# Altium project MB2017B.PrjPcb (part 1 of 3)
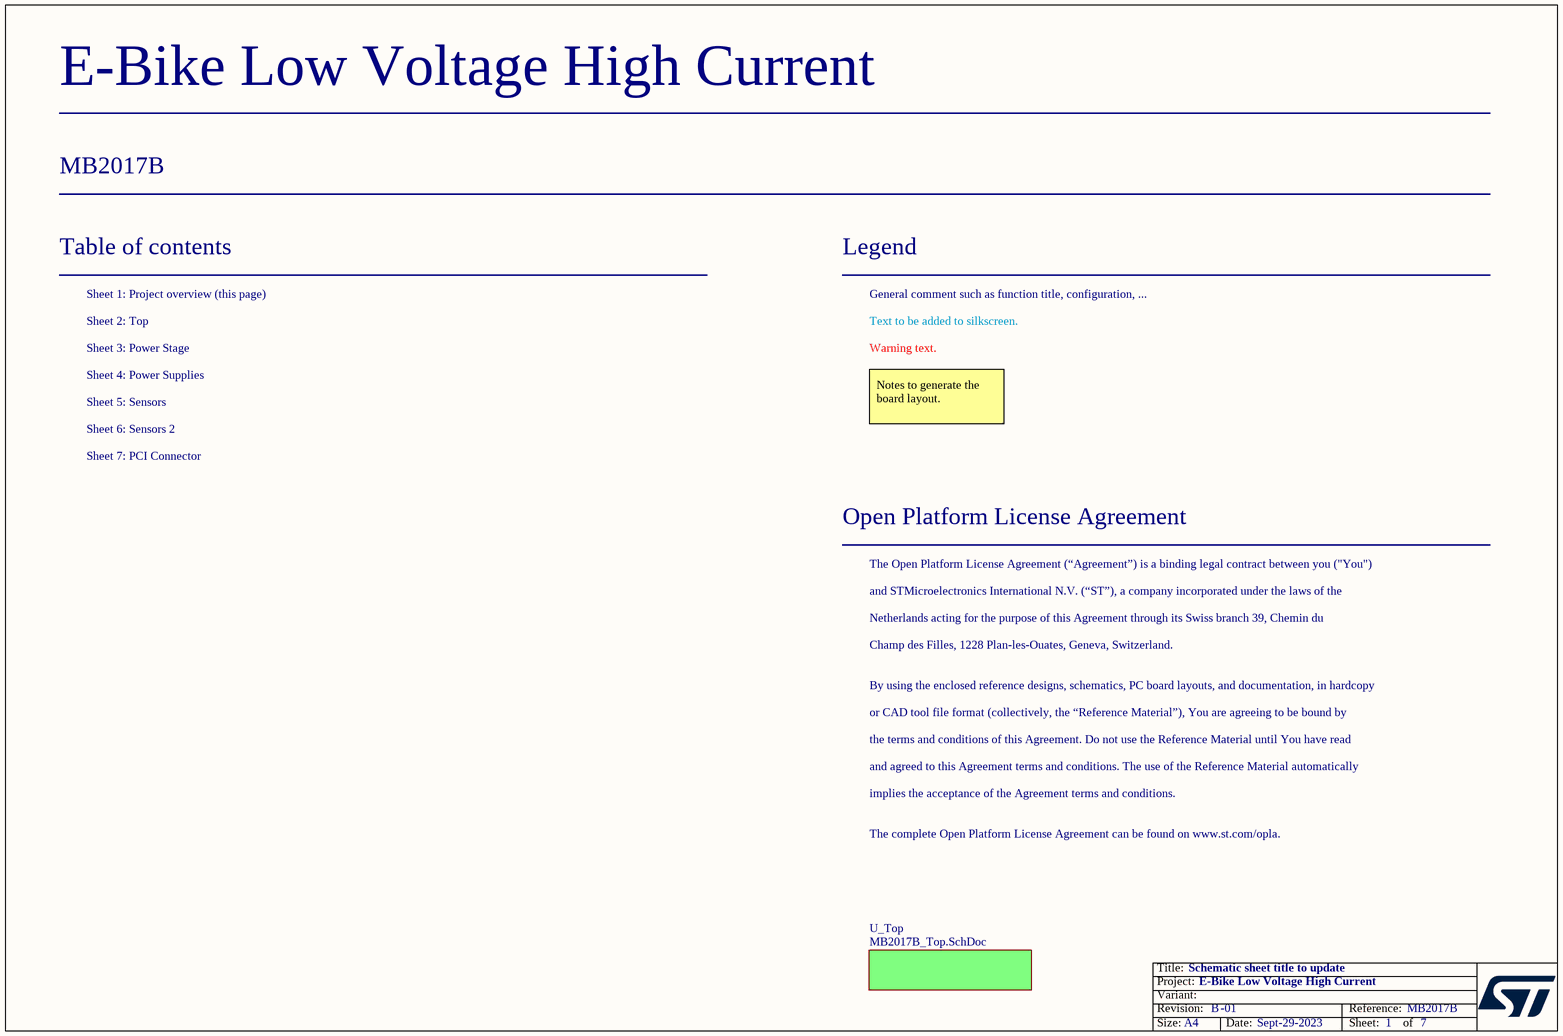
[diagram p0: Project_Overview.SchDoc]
Board_Assembly_Revision: 01; Board_Document_Date: Sept-29-2023; Board_Name: E-Bike Low Voltage High Current; Board_PCB_Revision: B; Board_Reference: MB2017B
7 sheets, 469 parts. Net scope: flat (ports and power ports of the same name join across sheets).
Board file: MB2017B.PcbDoc
Sheets:
  Project_Overview.SchDoc
    U_Top = MB2017B_Top.SchDoc
      U_Power_Supplies = Power_Supplies.SchDoc
      U_PCI_Connector = PCI_Connector.SchDoc
      U_Power_Stage = Power_Stage.SchDoc
      U_Sensors = Sensors.SchDoc
      U_Sensors_2 = Sensors_2.SchDoc

## Sheet Project_Overview.SchDoc: Schematic sheet title to update
size A4; Date: Not used; ApprovedBy: Not used; CheckedBy: Not used; Author: Not used; CompanyName: STMicroelectronics; DrawnBy: Not used; Engineer: Not used; Organization: Not used; Address1: Not used; Address2: Not used; Address3: Not used; Address4: Not used; DocumentNumber: Not used; Revision: Not used; SheetNumber: 1; SheetTotal: 7

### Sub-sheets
U_Top = MB2017B_Top.SchDoc: no entries

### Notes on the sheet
- Table of contents
- Sheet 1: Project overview (this page)
- Legend
- General comment such as function title, configuration, ...
- Sheet 2: Top
- Sheet 3: Power Stage
- Sheet 4: Power Supplies
- Text to be added to silkscreen.
- Warning text.
- Sheet 5: Sensors
- Sheet 6: Sensors 2
- Notes to generate the board layout.
- Sheet 7: PCI Connector
- Open Platform License Agreement
- The Open Platform License Agreement (“Agreement”) is a binding legal contract between you ("You")
- and STMicroelectronics International N.V. (“ST”), a company incorporated under the laws of the
- Netherlands acting for the purpose of this Agreement through its Swiss branch 39, Chemin du
- Champ des Filles, 1228 Plan-les-Ouates, Geneva, Switzerland.
- By using the enclosed reference designs, schematics, PC board layouts, and documentation, in hardcopy
- or CAD tool file format (collectively, the “Reference Material”), You are agreeing to be bound by
- the terms and conditions of this Agreement. Do not use the Reference Material until You have read
- and agreed to this Agreement terms and conditions. The use of the Reference Material automatically
- implies the acceptance of the Agreement terms and conditions.
- The complete Open Platform License Agreement can be found on www.st.com/opla.

## Sheet MB2017B_Top.SchDoc: Top
size A4; Date: Not used; ApprovedBy: Not used; CheckedBy: Not used; Author: Not used; CompanyName: STMicroelectronics; DrawnBy: Not used; Engineer: Not used; Organization: Not used; Address1: Not used; Address2: Not used; Address3: Not used; Address4: Not used; DocumentNumber: Not used; Revision: Not used; SheetNumber: 2; SheetTotal: 7
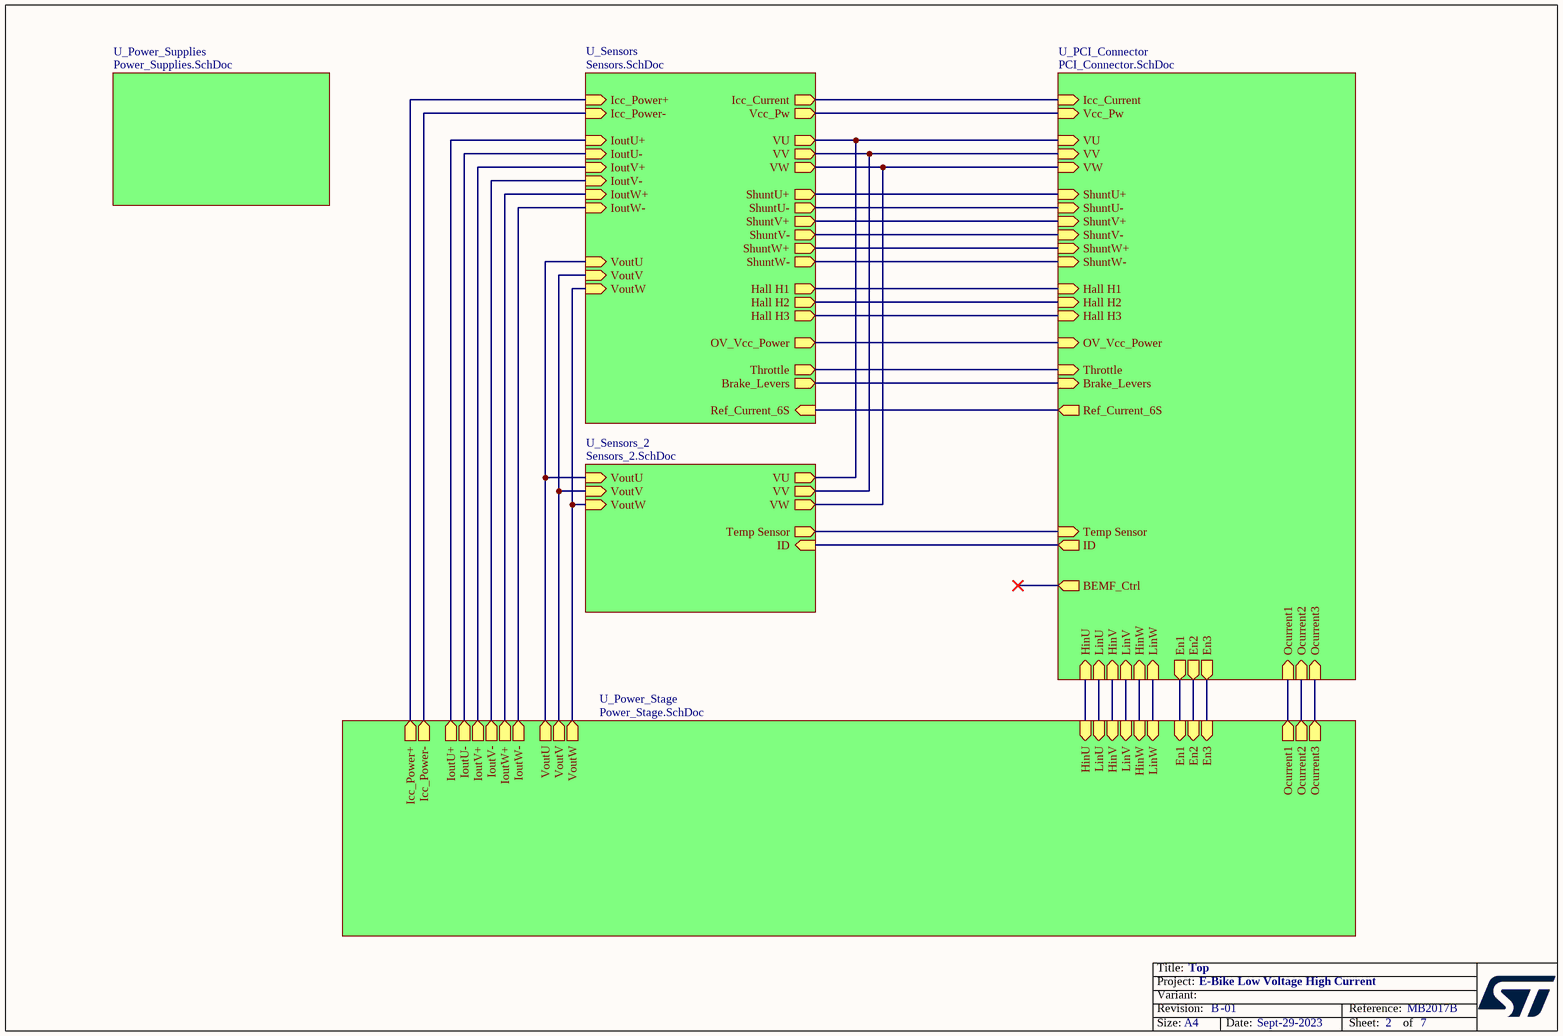
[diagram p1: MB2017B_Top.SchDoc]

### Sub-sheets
U_PCI_Connector = PCI_Connector.SchDoc: BEMF_Ctrl (out), HinU (in), LinU (in), HinV (in), LinV (in), HinW (in), LinW (in), Hall H1 (in), Hall H2 (in), Hall H3 (in), ShuntU- (in), ShuntU+ (in), ShuntV- (in), ShuntV+ (in), ShuntW- (in), ShuntW+ (in), VU (in), VV (in), VW (in), Temp Sensor (in), OV_Vcc_Power (in), Brake_Levers (in), Ref_Current_6S (out), Icc_Current (in), Throttle (in), Vcc_Pw (in), Ocurrent2 (in), En3 (out), Ocurrent3 (in), En1 (out), En2 (out), Ocurrent1 (in), ID (out)
U_Power_Stage = Power_Stage.SchDoc: VoutU (out), IoutU+ (out), IoutU- (out), HinU (in), LinU (in), IoutV+ (out), IoutV- (out), HinV (in), LinV (in), VoutW (out), IoutW+ (out), IoutW- (out), HinW (in), LinW (in), Icc_Power+ (out), Icc_Power- (out), En1 (in), En2 (in), Ocurrent3 (out), Ocurrent2 (out), En3 (in), Ocurrent1 (out), VoutV (out)
U_Power_Supplies = Power_Supplies.SchDoc: no entries
U_Sensors = Sensors.SchDoc: Icc_Power+ (in), Icc_Power- (in), Icc_Current (out), IoutU+ (in), IoutU- (in), IoutV+ (in), IoutV- (in), IoutW+ (in), IoutW- (in), VoutU (in), VoutV (in), VoutW (in), VU (out), VV (out), VW (out), ShuntU- (out), ShuntV- (out), ShuntW- (out), ShuntU+ (out), ShuntV+ (out), ShuntW+ (out), OV_Vcc_Power (out), Hall H1 (out), Hall H2 (out), Hall H3 (out), Throttle (out), Brake_Levers (out), Vcc_Pw (out), Ref_Current_6S (in)
U_Sensors_2 = Sensors_2.SchDoc: VoutU (in), VU (out), VoutV (in), VoutW (in), VW (out), VV (out), Temp Sensor (out), ID (in)

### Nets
(unnamed): sheet U_PCI_Connector/HinU, sheet U_Power_Stage/HinU
(unnamed): sheet U_PCI_Connector/LinU, sheet U_Power_Stage/LinU  [a separate net that carries the same name]
(unnamed): sheet U_PCI_Connector/HinV, sheet U_Power_Stage/HinV  [a separate net that carries the same name]
(unnamed): sheet U_PCI_Connector/LinV, sheet U_Power_Stage/LinV  [a separate net that carries the same name]
(unnamed): sheet U_PCI_Connector/HinW, sheet U_Power_Stage/HinW  [a separate net that carries the same name]
(unnamed): sheet U_PCI_Connector/LinW, sheet U_Power_Stage/LinW  [a separate net that carries the same name]
(unnamed): sheet U_PCI_Connector/Hall H1, sheet U_Sensors/Hall H1  [a separate net that carries the same name]
(unnamed): sheet U_PCI_Connector/Hall H2, sheet U_Sensors/Hall H2  [a separate net that carries the same name]
(unnamed): sheet U_PCI_Connector/Hall H3, sheet U_Sensors/Hall H3  [a separate net that carries the same name]
(unnamed): sheet U_PCI_Connector/ShuntU-, sheet U_Sensors/ShuntU-  [a separate net that carries the same name]
(unnamed): sheet U_PCI_Connector/ShuntU+, sheet U_Sensors/ShuntU+  [a separate net that carries the same name]
(unnamed): sheet U_PCI_Connector/ShuntV-, sheet U_Sensors/ShuntV-  [a separate net that carries the same name]
(unnamed): sheet U_PCI_Connector/ShuntV+, sheet U_Sensors/ShuntV+  [a separate net that carries the same name]
(unnamed): sheet U_PCI_Connector/ShuntW-, sheet U_Sensors/ShuntW-  [a separate net that carries the same name]
(unnamed): sheet U_PCI_Connector/ShuntW+, sheet U_Sensors/ShuntW+  [a separate net that carries the same name]
(unnamed): sheet U_PCI_Connector/VU, sheet U_Sensors/VU, sheet U_Sensors_2/VU  [a separate net that carries the same name]
(unnamed): sheet U_PCI_Connector/VV, sheet U_Sensors/VV, sheet U_Sensors_2/VV  [a separate net that carries the same name]
(unnamed): sheet U_PCI_Connector/VW, sheet U_Sensors/VW, sheet U_Sensors_2/VW  [a separate net that carries the same name]
(unnamed): sheet U_PCI_Connector/Temp Sensor, sheet U_Sensors_2/Temp Sensor  [a separate net that carries the same name]
(unnamed): sheet U_PCI_Connector/OV_Vcc_Power, sheet U_Sensors/OV_Vcc_Power  [a separate net that carries the same name]
(unnamed): sheet U_PCI_Connector/Brake_Levers, sheet U_Sensors/Brake_Levers  [a separate net that carries the same name]
(unnamed): sheet U_PCI_Connector/Ref_Current_6S, sheet U_Sensors/Ref_Current_6S  [a separate net that carries the same name]
(unnamed): sheet U_PCI_Connector/Icc_Current, sheet U_Sensors/Icc_Current  [a separate net that carries the same name]
(unnamed): sheet U_PCI_Connector/Throttle, sheet U_Sensors/Throttle  [a separate net that carries the same name]
(unnamed): sheet U_PCI_Connector/Vcc_Pw, sheet U_Sensors/Vcc_Pw  [a separate net that carries the same name]
(unnamed): sheet U_PCI_Connector/Ocurrent2, sheet U_Power_Stage/Ocurrent2  [a separate net that carries the same name]
(unnamed): sheet U_PCI_Connector/En3, sheet U_Power_Stage/En3  [a separate net that carries the same name]
(unnamed): sheet U_PCI_Connector/Ocurrent3, sheet U_Power_Stage/Ocurrent3  [a separate net that carries the same name]
(unnamed): sheet U_PCI_Connector/En1, sheet U_Power_Stage/En1  [a separate net that carries the same name]
(unnamed): sheet U_PCI_Connector/En2, sheet U_Power_Stage/En2  [a separate net that carries the same name]
(unnamed): sheet U_PCI_Connector/Ocurrent1, sheet U_Power_Stage/Ocurrent1  [a separate net that carries the same name]
(unnamed): sheet U_PCI_Connector/ID, sheet U_Sensors_2/ID  [a separate net that carries the same name]
(unnamed): sheet U_Power_Stage/VoutU, sheet U_Sensors/VoutU, sheet U_Sensors_2/VoutU  [a separate net that carries the same name]
(unnamed): sheet U_Power_Stage/IoutU+, sheet U_Sensors/IoutU+  [a separate net that carries the same name]
(unnamed): sheet U_Power_Stage/IoutU-, sheet U_Sensors/IoutU-  [a separate net that carries the same name]
(unnamed): sheet U_Power_Stage/IoutV+, sheet U_Sensors/IoutV+  [a separate net that carries the same name]
(unnamed): sheet U_Power_Stage/IoutV-, sheet U_Sensors/IoutV-  [a separate net that carries the same name]
(unnamed): sheet U_Power_Stage/VoutW, sheet U_Sensors/VoutW, sheet U_Sensors_2/VoutW  [a separate net that carries the same name]
(unnamed): sheet U_Power_Stage/IoutW+, sheet U_Sensors/IoutW+  [a separate net that carries the same name]
(unnamed): sheet U_Power_Stage/IoutW-, sheet U_Sensors/IoutW-  [a separate net that carries the same name]
(unnamed): sheet U_Power_Stage/Icc_Power+, sheet U_Sensors/Icc_Power+  [a separate net that carries the same name]
(unnamed): sheet U_Power_Stage/Icc_Power-, sheet U_Sensors/Icc_Power-  [a separate net that carries the same name]
(unnamed): sheet U_Power_Stage/VoutV, sheet U_Sensors/VoutV, sheet U_Sensors_2/VoutV  [a separate net that carries the same name]

## Sheet Power_Supplies.SchDoc: Power Supplies
size A3; Date: Not used; ApprovedBy: Not used; CheckedBy: Not used; Author: Not used; CompanyName: STMicroelectronics; DrawnBy: Not used; Engineer: Not used; Organization: Not used; Address1: Not used; Address2: Not used; Address3: Not used; Address4: Not used; DocumentNumber: Not used; Revision: Not used; SheetNumber: 4; SheetTotal: 7
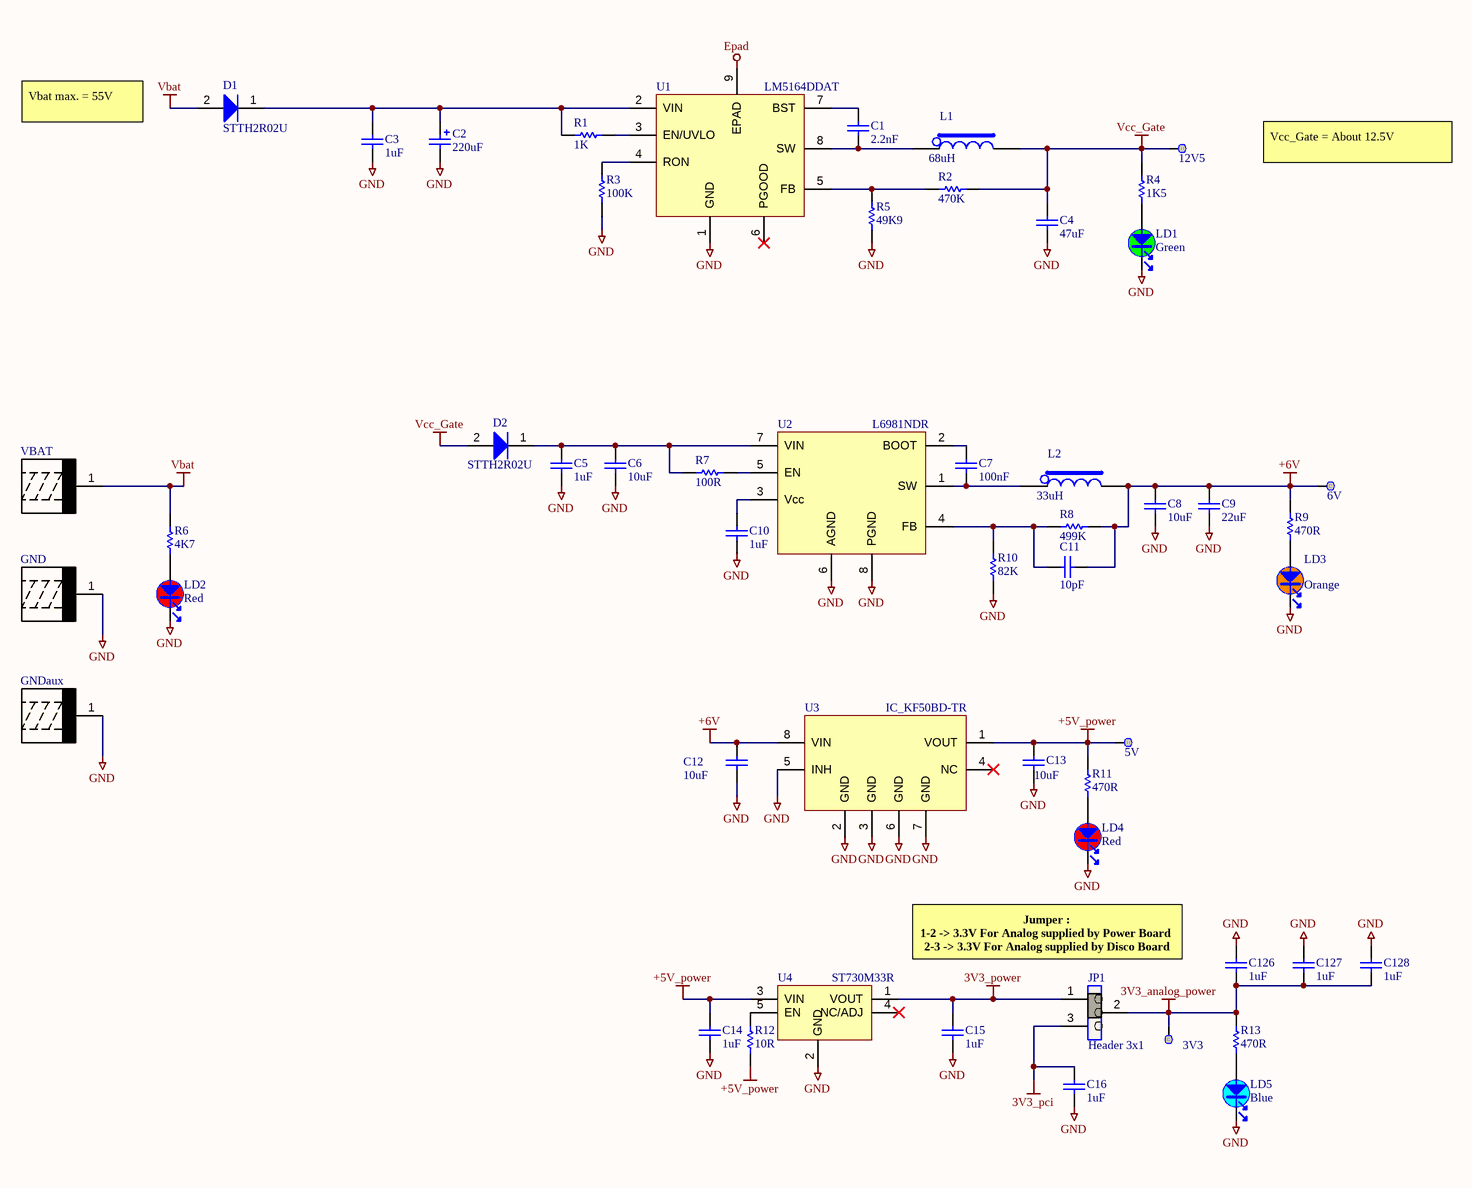
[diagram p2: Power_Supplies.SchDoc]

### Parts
3V3  Test Point  [TP_SMD_1MM]  (value not drawn)  (no BOM)
5V  Test Point  [TP_SMD_1MM]  (value not drawn)  (no BOM)
6V  Test Point  [TP_SMD_1MM]  (value not drawn)  (no BOM)
12V5  Test Point  [TP_SMD_1MM]  (value not drawn)  (no BOM)
C1  value 2.2nF  [C0603_H0P8]  (hidden comment: Capacitor)
C2  value 220uF  [CPOL_TDK_B41858C9227M000_H25]  (hidden comment: Cap_POL_TANA)
C3  value 1uF  [C1206_H1P6]  (hidden comment: Capacitor)
C4  value 47uF  [C1206_H1P6]  (hidden comment: Capacitor)
C5  value 1uF  [C0805_H0P85]  (hidden comment: Capacitor)
C6  value 10uF  [C1206_H1P6]  (hidden comment: Capacitor)
C7  value 100nF  [C0805_H0P85]  (hidden comment: Capacitor)
C8  value 10uF  [C1206_H1P6]  (hidden comment: Capacitor)
C9  value 22uF  [C1206_H1P6]  (hidden comment: Capacitor)
C10  value 1uF  [C0805_H0P85]  (hidden comment: Capacitor)
C11  value 10pF  [C0603]  (hidden comment: Capacitor)
C12  value 10uF  [C1206_H1P6]  (hidden comment: Capacitor)
C13  value 10uF  [C1206_H1P6]  (hidden comment: Capacitor)
C14  value 1uF  [C0805_H0P85]  (hidden comment: Capacitor)
C15  value 1uF  [C0805_H0P85]  (hidden comment: Capacitor)
C16  value 1uF  [C0805_H0P85]  (hidden comment: Capacitor)
C126  value 1uF  [C0805_H0P85]  (hidden comment: Capacitor)
C127  value 1uF  [C0805_H0P85]  (hidden comment: Capacitor)
C128  value 1uF  [C0805_H0P85]  (hidden comment: Capacitor)
D1  value STTH2R02U  [DIO_SMB_1K_2A]  (hidden comment: DIODE_1K_2A)
D2  value STTH2R02U  [DIO_SMB_1K_2A]  (hidden comment: DIODE_1K_2A)
GND  CON_M4_SNAP_IN_THR_KEYSTONE_7798  [CON_KEYSTONE_M4-SNAP_7798]  (value not drawn)
GNDaux  CON_M4_SNAP_IN_THR_KEYSTONE_7798  [CON_KEYSTONE_M4-SNAP_7798]  (value not drawn)
JP1  value Header 3x1  [CON_SAMTEC_TSW-103-07-F-S]  (hidden comment: Jumper_Header 3x1 Fitted 1-2)
L1  value 68uH  [IND_WURTH_7447714680]  (hidden comment: INDUCTOR_POWER_WINDING)
L2  value 33uH  [IND_COILCRAFT_MSS1038T-333MLC]  (hidden comment: INDUCTOR_POWER_WINDING)
LD1  value Green  [LED_0603_VISHAY_VLMTG1300-GS08_GREEN_1A2K_H0P8]  (hidden comment: LED_green)
LD2  value Red  [LED_0603_VISHAY_VLMS1300-GS08_RED_1A2K_H0P8]  (hidden comment: LED_red)
LD3  value Orange  [LED_0603_VISHAY_VLMO1300-GS08_ORANGE_1A2K_H0P8]  (hidden comment: LED_orange)
LD4  value Red  [LED_0603_VISHAY_VLMS1300-GS08_RED_1A2K_H0P8]  (hidden comment: LED_red)
LD5  value Blue  [LED_0603_VISHAY_VLMB1300-GS08_BLUE_1A2K_H0P8]  (hidden comment: LED_blue)
R1  value 1K  [R0603]  (hidden comment: Resistor)
R2  value 470K  [R0603]  (hidden comment: Resistor)
R3  value 100K  [R0603]  (hidden comment: Resistor)
R4  value 1K5  [R0805]  (hidden comment: Resistor)
R5  value 49K9  [R0603]  (hidden comment: Resistor)
R6  value 4K7  [R0805]  (hidden comment: Resistor)
R7  value 100R  [R0603]  (hidden comment: Resistor)
R8  value 499K  [R0603_H0P45]  (hidden comment: Resistor)
R9  value 470R  [R0805]  (hidden comment: Resistor)
R10  value 82K  [R0603]  (hidden comment: Resistor)
R11  value 470R  [R0805]  (hidden comment: Resistor)
R12  value 10R  [R0805_H0P5]  (hidden comment: Resistor)
R13  value 470R  [R0805]  (hidden comment: Resistor)
U1  LM5164DDAT  [ICC_SO8-EPAD_DDA_5X4_P127]
U2  value L6981NDR  [ICC_SO8_5X4_P127]  (hidden comment: IC_L6981NDR)
U3  IC_KF50BD-TR  [ICC_SO8_5X4_P127]
U4  ST730M33R  [ICC_SOT23-5L_H1P45]
VBAT  CON_M4_SNAP_IN_THR_KEYSTONE_7798  [CON_KEYSTONE_M4-SNAP_7798]  (value not drawn)

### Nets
3V3_analog_power: 3V3.1 C126.2 C127.2 C128.2 JP1.2 R13.2
3V3_pci: C16.2 JP1.3
3V3_power: C15.2 JP1.1 U4.1(VOUT)
+5V_power: 5V.1 C13.2 C14.2 R11.2 R12.1 U3.1(VOUT) U4.3(VIN)
+6V: 6V.1 C8.2 C9.2 C11.2 C12.2 L2.2 R8.2 R9.2 U3.8(VIN)
Epad: U1.9(EPAD)
GND: C2.2 C3.1 C4.1 C5.1 C6.1 C8.1 C9.1 C10.1 C12.1 C13.1 C14.1 C15.1 C16.1 C126.1 C127.1 C128.1 GND.1 GNDaux.1 LD1.2 LD2.2 LD3.2 LD4.2 LD5.2 R3.1 R5.1 R10.1 U1.1(GND) U2.6(AGND) U2.8(PGND) U3.2(GND) U3.3(GND) U3.5(INH) U3.6(GND) U3.7(GND) U4.2(GND)
Vbat: D1.2(A) R6.2 VBAT.1
Vcc_Gate: 12V5.1 C4.2 D2.2(A) L1.2 R2.2 R4.2
NetC1_1: C1.1 L1.1 U1.8(SW)
NetC1_2: C1.2 U1.7(BST)
NetC2_1: C2.1 C3.2 D1.1(K) R1.1 U1.2(VIN)
NetC5_2: C5.2 C6.2 D2.1(K) R7.1 U2.7(VIN)
NetC7_1: C7.1 L2.1 U2.1(SW)
NetC7_2: C7.2 U2.2(BOOT)
NetC10_2: C10.2 U2.3(Vcc)
NetC11_1: C11.1 R8.1 R10.2 U2.4(FB)
NetLD1_1: LD1.1 R4.1
NetLD2_1: LD2.1 R6.1
NetLD3_1: LD3.1 R9.1
NetLD4_1: LD4.1 R11.1
NetLD5_1: LD5.1 R13.1
NetR1_2: R1.2 U1.3(EN/UVLO)
NetR2_1: R2.1 R5.2 U1.5(FB)
NetR3_2: R3.2 U1.4(RON)
NetR7_2: R7.2 U2.5(EN)
NetR12_2: R12.2 U4.5(EN)

Not connected (* = marked no-connect by the designer): U1 6(PGOOD)*; U3 4(NC)*; U4 4(NC/ADJ)*

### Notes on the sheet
- Vbat max. = 55V
- Vcc_Gate = About 12.5V
- Jumper :
  1-2 -> 3.3V For Analog supplied by Power Board
  2-3 -> 3.3V For Analog supplied by Disco Board

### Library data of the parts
3V3 5V 6V 12V5 = MCD-00074: Test Point 1mm; Part_Type: Misc; Part_Preference: Recommended; ShowFields: YES; ID: 2518; Component_Country_Of_Origin: Unknown
C1 = MCD-02457: Capacitor, MLCC, 2.2nF, 50V, C0G/NPO, +/-5%, 0603, T=0,8mm; Part_Preference: Recommended; Manufacturer: YAGEO; Manufacturer_Part_Number: CC0603JRNPO9BN222; Order_Code_RS: 200-6484; Component_Country_Of_Origin: China; ShowFields: YES; ID: 4563
C2 = MCD-03694: Capacitor, Aluminum Electrolytic Low ESR, 220uF, 100V, 0.099Ohms, +/-20%, 16x25mm, T=25mm; Part_Preference: Recommended; Manufacturer: TDK; Manufacturer_Part_Number: B41858C9227M000; Order_Code_RS: 261-0666; ShowFields: YES; ID: 5810; Component_Country_Of_Origin: China°
C3 = MCD-03394: Capacitor, MLCC, 1uF, 100V, X7R, 10%, 1206, T=1.6mm; Part_Preference: Recommended; Manufacturer: TDK; Manufacturer_Part_Number: C3216X7R2A105K160AA; Order_Code_RS: 242-7428; Component_Country_Of_Origin: Japan°; ShowFields: YES; ID: 5510
C4 = MCD-01517: Capacitor, MLCC, 47uF, 25V, X5R, +/-20%, 1206, T=1.6mm; Part_Preference: Forbidden; Manufacturer: TDK; Manufacturer_Part_Number: C3216X5R1E476M160AC; Order_Code_RS: 108-4056; ShowFields: YES; ID: 3617
C5 C10 C14-C16 C126-C128 = MCD-01550: Capacitor, MLCC, 1uF, 16V, X5R, +/-10%, 0805, T=0.85mm; Part_Preference: Recommended; Manufacturer: YAGEO; Manufacturer_Part_Number: CC0805KRX5R7BB105; Component_Country_Of_Origin: China; ShowFields: YES; ID: 3650
C6 C8 C12 C13 = MCD-02610: Capacitor, MLCC, 10uF, 25V, X5R, +/-10%, 1206, T=1.6mm; Part_Preference: Recommended; Manufacturer: YAGEO; Manufacturer_Part_Number: CC1206KKX5R8BB106; Order_Code_RS: 1991983; ShowFields: YES; ID: 4716; Component_Country_Of_Origin: China
C7 = MCD-01525: Capacitor, MLCC, 100nF, 50V, X7R, +/-10%, 0805, T=0.85mm; BMS_Part_Number: 9142249; Part_Preference: Recommended; Manufacturer: YAGEO; Manufacturer_Part_Number: CC0805KRX7R9BB104; Order_Code_RS: 669-8842; Component_Country_Of_Origin: China; ShowFields: YES; ID: 3625
C9 = MCD-02328: Capacitor, MLCC, 22uF, 25V, X5R, +/-10%, 1206, T=1,6mm; Part_Preference: Recommended; Manufacturer: SAMSUNG ELECTRO-MECHANICS; Manufacturer_Part_Number: CL31A226KAHNNNE; Order_Code_RS: 766-6708; Component_Country_Of_Origin: China°; ShowFields: YES; ID: 4434
C11 = MCD-00637: Capacitor, MLCC, 10pF, 50V, NPO, +/-5%, 0603, T=0.8mm; Part_Preference: Recommended; Manufacturer: YAGEO; Manufacturer_Part_Number: CC0603JRNPO9BN100; Order_Code_RS: 616-9054; Component_Country_Of_Origin: China; ShowFields: YES; ID: 3104
D1 D2 = MCD-03397: Diode, Ultrafast Recovery Rectifier, 0V89, 2A, 200V, DO-214AA; Part_Preference: Forbidden; Manufacturer: STMICROELECTRONICS; Order_Code_RS: 249-707; Component_Country_Of_Origin: China; ShowFields: YES; ID: 5513
GND GNDaux VBAT = MCD-03715: Connector, M4, SNAP IN, 1x1, VR, TH, T=11.68mm; Part_Preference: Not recommended; Manufacturer: KEYSTONE ELECTRONICS; Manufacturer_Part_Number: 7798; Value: TERM SCREW M4 PCB 30A; ShowFields: YES; ID: 5831; Component_Country_Of_Origin: Unknown
JP1 = MCD-01905: Header, 3x1, 2.54mm, VR, TH, T=5.84mm/2.54mm; Part_Type: Connector; Part_Preference: Recommended; Manufacturer: SAMTEC; Manufacturer_Part_Number: TSW-103-07-G-S; Order_Code_RS: 161-2521; Component_Country_Of_Origin: China, Costa Rica, Malaysia, USA, Vietnam; ShowFields: YES; ID: 4005
L1 = MCD-03696: Inductor, 68uH, +/-20%, 1.9A, 110mR, 10.5x10.3mm, T=5mm; Part_Preference: Recommended; Manufacturer: WURTH ELEKTRONIK; Manufacturer_Part_Number: 7447714680; Order_Code_RS: 789-6993; ShowFields: YES; ID: 5812; Component_Country_Of_Origin: China
L2 = MCD-03623: Inductor, 33uH, +/-20%, 2.3A, 93mR, SMT, T=3.8mm; Part_Preference: Recommended; Manufacturer: COILCRAFT; Manufacturer_Part_Number: MSS1038T-333MLC; Component_Country_Of_Origin: China; ShowFields: YES; ID: 5739
LD1 = MCD-00589: LED, Green, 3V2, 20mA, 0603; Part_Type: Display; Part_Preference: Recommended; Manufacturer: VISHAY; Manufacturer_Part_Number: VLMTG1300-GS08; Order_Code_RS: 7730452; Component_Country_Of_Origin: China; ShowFields: YES; ID: 3157
LD2 LD4 = MCD-00587: LED, Red, 2V, 20mA, 0603; Part_Type: Display; Part_Preference: Recommended; Manufacturer: VISHAY; Manufacturer_Part_Number: VLMS1300-GS08; Full_Alternate_Internal_Part_Number: MCD-02401; Component_Country_Of_Origin: China; ShowFields: YES; ID: 3154
LD3 = MCD-00591: LED, Orange, 2V, 20mA, 0603; Part_Type: Display; Part_Preference: Recommended; Manufacturer: VISHAY; Manufacturer_Part_Number: VLMO1300-GS08; Order_Code_RS: 7730446; Component_Country_Of_Origin: China; ShowFields: YES; ID: 3153
LD5 = MCD-00584: LED, Blue, 3V3, 20mA, 0603; Part_Type: Display; Part_Preference: Recommended; Manufacturer: VISHAY; Manufacturer_Part_Number: VLMB1300-GS08; Partial_Alternate_Internal_Part_Number: MCD-02786; Order_Code_RS: 7730430; Component_Country_Of_Origin: China; ShowFields: YES; ID: 3160; Alternate_EMS: A
R1 = MCD-00070: Resistor, 1K, 0603, +/-1%, 1/10W; Part_Preference: Recommended; Manufacturer: YAGEO; Manufacturer_Part_Number: RC0603FR-071KL; Order_Code_RS: 9238484RL; Component_Country_Of_Origin: China; ShowFields: YES; ID: 2522
R2 = MCD-00484: Resistor, 470K, 0603, +/-1%, 1/10W; BMS_Part_Number: 9129978; Part_Preference: Recommended; Manufacturer: YAGEO; Manufacturer_Part_Number: RC0603FR-07470KL; Component_Country_Of_Origin: China; ShowFields: YES; ID: 2792
R3 = MCD-00223: Resistor, 100K, 0603, +/- 1%, 1/10W; Part_Preference: Recommended; Manufacturer: YAGEO; Manufacturer_Part_Number: RC0603FR-07100KL; Component_Country_Of_Origin: China; ShowFields: YES; ID: 2647
R4 = MCD-03531: Resistor, 1K5, 0805, +/-1%, 1/8W; Part_Preference: Recommended; Manufacturer: YAGEO; Manufacturer_Part_Number: RC0805FR-071K5L; Order_Code_RS: 9237518; Component_Country_Of_Origin: China; ShowFields: YES; ID: 5647
R5 = MCD-01171: Resistor, 49K9, 0603, +/-1%, 1/10W; Part_Preference: Recommended; Manufacturer: YAGEO; Manufacturer_Part_Number: RC0603FR-0749K9L; Component_Country_Of_Origin: China; ShowFields: YES; ID: 3324
R6 = MCD-03530: Resistor, 4K7, 0805, +/-1%, 1/8W; Part_Preference: Recommended; Manufacturer: YAGEO; Manufacturer_Part_Number: RC0805FR-074K7L; Order_Code_RS: 9237704; Component_Country_Of_Origin: China; ShowFields: YES; ID: 5646
R7 = MCD-00224: Resistor, 100R, 0603, +/-1%, 1/10W; Part_Preference: Recommended; Manufacturer: YAGEO; Manufacturer_Part_Number: RC0603FR-07100RL; Component_Country_Of_Origin: China; ShowFields: YES; ID: 2643
R8 = MCD-01720: Resistor, 499K, 0603, +/-1%, 1/10W; Part_Preference: Recommended; Manufacturer: YAGEO; Manufacturer_Part_Number: RC0603FR-07499KL; Component_Country_Of_Origin: China; ShowFields: YES; ID: 3820
R9 R11 R13 = MCD-03534: Resistor, 470R, 0805, +/-1%, 1/8W; Part_Preference: Recommended; Manufacturer: YAGEO; Manufacturer_Part_Number: RC0805FR-07470RL; Order_Code_RS: 9237445; Component_Country_Of_Origin: China; ShowFields: YES; ID: 5650
R10 = MCD-00532: Resistor, 82K, 0603, +/-1%, 1/10W; Part_Preference: Recommended; Manufacturer: YAGEO; Manufacturer_Part_Number: RC0603FR-0782KL; Component_Country_Of_Origin: China; ShowFields: YES; ID: 3213
R12 = MCD-01548: Resistor, 10R, 0805, +/-1%, 1/8W; BMS_Part_Number: 9129303; Part_Preference: Recommended; Manufacturer: YAGEO; Manufacturer_Part_Number: RC0805FR-0710RL; Order_Code_RS: 618-5179; Component_Country_Of_Origin: China; ShowFields: YES; ID: 3648
U1 = MCD-03695: Regulator, 1A, STEP DOWN SWITCHING, 6V To 100V, 1MHz; Part_Type: IC; Part_Preference: Recommended; Manufacturer: TEXAS INSTRUMENTS; ShowFields: YES; ID: 5811; Component_Country_Of_Origin: Mexico
U2 = MCD-03622: Regulator, 1.5A, SYNCHRONOUS STEP DOWN LNM SWITCHING CONVERTER , 3V5 to 38V, 400KHz; Part_Type: IC; Part_Preference: Recommended; Manufacturer: STMICROELECTRONICS; Order_code_RS: 216-7851; Component_Country_Of_Origin: China; ShowFields: YES; ID: 5738
U3 = MCD-03540: DC Input voltage is from -0.5 V to 20V; Part_Type: IC; Part_Preference: Not recommended; Manufacturer: STMICROELECTRONICS; Order_code_RS: 795-8448; Component_Country_Of_Origin: China; ShowFields: YES; ID: 5656
U4 = MCD-02514: LDO, 300mA, 28V, Low-dropout voltage, with 5uA quiescent current; Part_Type: IC; Part_Preference: Recommended; Manufacturer: STMICROELECTRONICS; Component_Country_Of_Origin: Malaysia; ShowFields: YES; ID: 4620

## Sheet PCI_Connector.SchDoc: PCI Connector
size A3; Date: Not used; ApprovedBy: Not used; CheckedBy: Not used; Author: Not used; CompanyName: STMicroelectronics; DrawnBy: Not used; Engineer: Not used; Organization: Not used; Address1: Not used; Address2: Not used; Address3: Not used; Address4: Not used; DocumentNumber: Not used; Revision: Not used; SheetNumber: 7; SheetTotal: 7
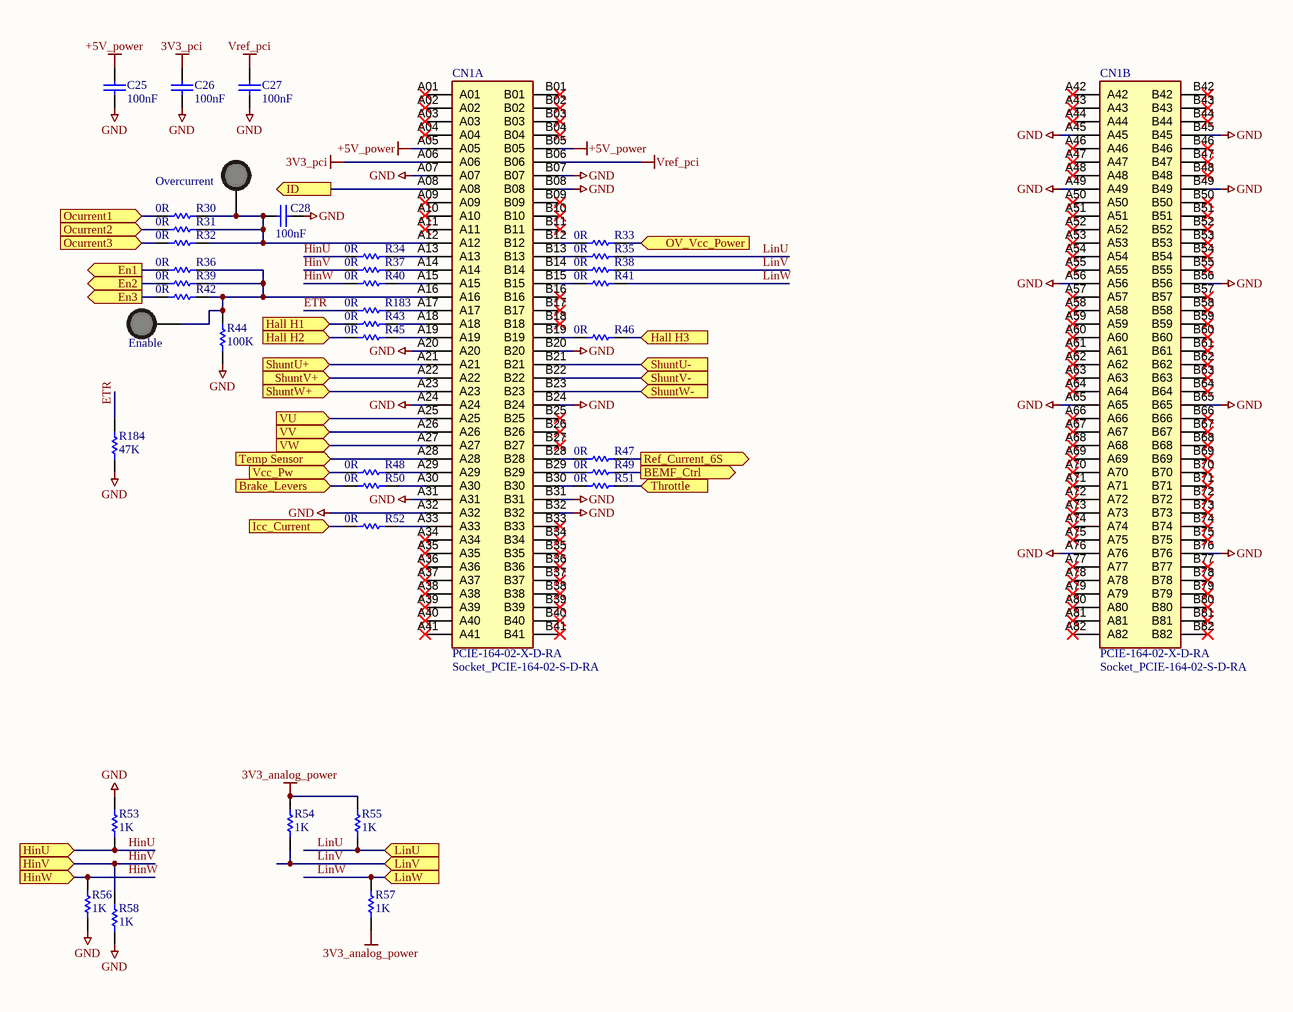
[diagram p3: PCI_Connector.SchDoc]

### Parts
C25  value 100nF  [C0603]  (hidden comment: Capacitor)
C26  value 100nF  [C0603]  (hidden comment: Capacitor)
C27  value 100nF  [C0603]  (hidden comment: Capacitor)
C28  value 100nF  [C0603]  (hidden comment: Capacitor)
CN1  PCIE-164-02-X-D-RA  value Socket_PCIE-164-02-S-D-RA  [CON_SAMTEC_PCIE-164-02-X-D-RA]  (parts A,B of 2)
Enable  Test_pin_conn_black - NOT CONNECTED  [TP_PTH-1P02MM_TEST-TERMINAL_RS_101-2391_BLACK]  (value not drawn)
Overcurrent  Test_pin_conn_black - NOT CONNECTED  [TP_PTH-1P02MM_TEST-TERMINAL_RS_101-2391_BLACK]  (value not drawn)
R30  value 0R  [R0805]  (hidden comment: Resistor)
R31  value 0R  [R0805]  (hidden comment: Resistor)
R32  value 0R  [R0805]  (hidden comment: Resistor)
R33  value 0R  [R0805]  (hidden comment: Resistor)
R34  value 0R  [R0805]  (hidden comment: Resistor)
R35  value 0R  [R0805]  (hidden comment: Resistor)
R36  value 0R  [R0805]  (hidden comment: Resistor)
R37  value 0R  [R0805]  (hidden comment: Resistor)
R38  value 0R  [R0805]  (hidden comment: Resistor)
R39  value 0R  [R0805]  (hidden comment: Resistor)
R40  value 0R  [R0805]  (hidden comment: Resistor)
R41  value 0R  [R0805]  (hidden comment: Resistor)
R42  value 0R  [R0805]  (hidden comment: Resistor)
R43  value 0R  [R0805]  (hidden comment: Resistor)
R44  value 100K  [R0603]  (hidden comment: Resistor)
R45  value 0R  [R0805]  (hidden comment: Resistor)
R46  value 0R  [R0805]  (hidden comment: Resistor)
R47  value 0R  [R0805]  (hidden comment: Resistor)
R48  value 0R  [R0805]  (hidden comment: Resistor)
R49  value 0R  [R0805]  (hidden comment: Resistor)
R50  value 0R  [R0805]  (hidden comment: Resistor)
R51  value 0R  [R0805]  (hidden comment: Resistor)
R52  value 0R  [R0805]  (hidden comment: Resistor)
R53  value 1K  [R0603]  (hidden comment: Resistor)
R54  value 1K  [R0603]  (hidden comment: Resistor)
R55  value 1K  [R0603]  (hidden comment: Resistor)
R56  value 1K  [R0603]  (hidden comment: Resistor)
R57  value 1K  [R0603]  (hidden comment: Resistor)
R58  value 1K  [R0603]  (hidden comment: Resistor)
R183  value 0R  [R0805]  (hidden comment: Resistor)
R184  value 47K  [R0603]  (hidden comment: Resistor)

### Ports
BEMF_Ctrl (out), Brake_Levers (in), En1 (out), En2 (out), En3 (out), Hall H1 (in), Hall H2 (in), Hall H3 (in), HinU (in), HinV (in), HinW (in), Icc_Current (in), ID (out), LinU (in), LinV (in), LinW (in), Ocurrent1 (in), Ocurrent2 (in), Ocurrent3 (in), OV_Vcc_Power (in), Ref_Current_6S (out), ShuntU+ (in), ShuntU- (in), ShuntV+ (in), ShuntV- (in), ShuntW+ (in), ShuntW- (in), Temp Sensor (in), Throttle (in), Vcc_Pw (in), VU (in), VV (in), VW (in)

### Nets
3V3_analog_power: R54.2 R55.2 R57.1
3V3_pci: C26.1 CN1.A06
+5V_power: C25.1 CN1.A05 CN1.B05
GND: C25.2 C26.2 C27.2 C28.2 CN1.A07 CN1.A20 CN1.A24 CN1.A31 CN1.A32 CN1.A45 CN1.A49 CN1.A56 CN1.A65 CN1.A76 CN1.B07 CN1.B08 CN1.B20 CN1.B24 CN1.B31 CN1.B32 CN1.B45 CN1.B49 CN1.B56 CN1.B65 CN1.B76 R44.1 R53.2 R56.1 R58.1 R184.1
Vref_pci: C27.1 CN1.B06
BEMF_Ctrl: R49.1 ; port BEMF_Ctrl
Brake_Levers: R50.2 ; port Brake_Levers
En1: R36.2 ; port En1
En2: R39.2 ; port En2
En3: R42.2 ; port En3
ETR: R183.2 R184.2
Hall H1: R43.2 ; port Hall H1
Hall H2: R45.2 ; port Hall H2
Hall H3: R46.1 ; port Hall H3
HinU: R34.2 R53.1 ; port HinU
HinV: R37.2 R58.2 ; port HinV
HinW: R40.2 R56.2 ; port HinW
Icc_Current: R52.2 ; port Icc_Current
ID: CN1.A08 ; port ID
LinU: R35.1 R55.1 ; port LinU
LinV: R38.1 R54.1 ; port LinV
LinW: R41.1 R57.2 ; port LinW
Ocurrent1: R30.2 ; port Ocurrent1
Ocurrent2: R31.2 ; port Ocurrent2
Ocurrent3: R32.2 ; port Ocurrent3
OV_Vcc_Power: R33.1 ; port OV_Vcc_Power
Ref_Current_6S: R47.1 ; port Ref_Current_6S
ShuntU+: CN1.A21 ; port ShuntU+
ShuntU-: CN1.B21 ; port ShuntU-
ShuntV+: CN1.A22 ; port ShuntV+
ShuntV-: CN1.B22 ; port ShuntV-
ShuntW+: CN1.A23 ; port ShuntW+
ShuntW-: CN1.B23 ; port ShuntW-
Temp Sensor: CN1.A28 ; port Temp Sensor
Throttle: R51.1 ; port Throttle
Vcc_Pw: R48.2 ; port Vcc_Pw
VU: CN1.A25 ; port VU
VV: CN1.A26 ; port VV
VW: CN1.A27 ; port VW
NetC28_1: C28.1 CN1.A12 Overcurrent.1 R30.1 R31.1 R32.1
NetCN1_A13: CN1.A13 R34.1
NetCN1_A14: CN1.A14 R37.1
NetCN1_A15: CN1.A15 R40.1
NetCN1_A16: CN1.A16 Enable.1 R36.1 R39.1 R42.1 R44.2
NetCN1_A17: CN1.A17 R183.1
NetCN1_A18: CN1.A18 R43.1
NetCN1_A19: CN1.A19 R45.1
NetCN1_A29: CN1.A29 R48.1
NetCN1_A30: CN1.A30 R50.1
NetCN1_A33: CN1.A33 R52.1
NetCN1_B12: CN1.B12 R33.2
NetCN1_B13: CN1.B13 R35.2
NetCN1_B14: CN1.B14 R38.2
NetCN1_B15: CN1.B15 R41.2
NetCN1_B19: CN1.B19 R46.2
NetCN1_B28: CN1.B28 R47.2
NetCN1_B29: CN1.B29 R49.2
NetCN1_B30: CN1.B30 R51.2

Not connected (* = marked no-connect by the designer): CN1 A01* A02* A03* A04* A09* A10* A11* A34* A35* A36* A37* A38* A39* A40* A41* A42* A43* A44* A46* A47* A48* A50* A51* A52* A53* A54* A55* A57* A58* A59* A60* A61* A62* A63* A64* A66* A67* A68* A69* A70* A71* A72* A73* A74* A75* A77* A78* A79* A80* A81* A82* B01* B02* B03* B04* B09* B10* B11* B16* B17* B18* B25* B26* B27* B33* B34* B35* B36* B37* B38* B39* B40* B41* B42* B43* B44* B46* B47* B48* B50* B51* B52* B53* B54* B55* B57* B58* B59* B60* B61* B62* B63* B64* B66* B67* B68* B69* B70* B71* B72* B73* B74* B75* B77* B78* B79* B80* B81* B82*

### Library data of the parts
C25-C28 = MCD-01099: Capacitor, MLCC, 100nF, 50V, X7R, +/-10%, 0603, T=0.8mm; BMS_Part_Number: 9142278; Part_Preference: Recommended; Manufacturer: YAGEO; Manufacturer_Part_Number: CC0603KRX7R9BB104; Order_Code_RS: 669-8767; Component_Country_Of_Origin: China; ShowFields: YES; ID: 3397
CN1 = MCD-02664: Socket_PCIE, 164 pins, RA, TH, T=9,45mm; Part_Type: Connector; Part_Preference: Recommended; Manufacturer: SAMTEC; Manufacturer_Part_Number: PCIE-164-02-S-D-RA; Component_Country_Of_Origin: China, Costa Rica, Malaysia, Singapore, Taiwan, USA, Vietnam; ShowFields: YES; ID: 4770
Enable Overcurrent = MCD-00713: Black test terminal, Hole diameter=1.02mm; Part_Type: Misc; Part_Preference: Recommended; Manufacturer: VERO; Value: 20-2137; Order_Code_RS: 101-2391; Component_Country_Of_Origin: UK; ShowFields: YES; ID: 3032
R30-R43 R45-R52 R183 = MCD-00179: Resistor, 0R, 0805, +/-5%, 1/8W; Part_Preference: Recommended; Manufacturer: YAGEO; Manufacturer_Part_Number: RC0805JR-070RL; Component_Country_Of_Origin: China; ShowFields: YES; ID: 2685
R44 = MCD-00223: as R3 on sheet Power_Supplies
R53-R58 = MCD-00070: as R1 on sheet Power_Supplies
R184 = MCD-00222: Resistor, 47K, 0603, 1%, 1/10W; Part_Preference: Recommended; Manufacturer: YAGEO; Manufacturer_Part_Number: RC0603FR-0747KL; Component_Country_Of_Origin: China; ShowFields: YES; ID: 2645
